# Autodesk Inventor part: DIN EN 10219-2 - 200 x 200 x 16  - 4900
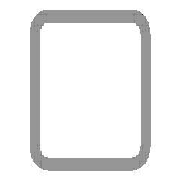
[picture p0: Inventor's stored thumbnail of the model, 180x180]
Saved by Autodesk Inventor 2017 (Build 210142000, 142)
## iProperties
IsCustomPart: 1
Created: 2017-11
Part Number: DIN EN 10219-2 - 200 x 200 x 16  - 4900
Material: Steel, Mild
Description: Cold formed welded structural hollow sections of non-alloy and fine grain structural steel
Document SubType Name: Modeling
Standard: DIN
Designer: iusti
Standard Revision: 2006-07
Standards Organization: DIN
Language: en-US
Size Designation: 200 x 200 x 16
Categories: <MemberInstance><Categories><Category DisplayName="Structural Shapes" InternalName="089c4875-fa83-4c05-b084-43b9cc11f5ed" Mnemonic="GRDR"><CategoryParameter Dis
Stock Number: 200 x 200 x 16
Density: 7.85 g/cm^3
Appearance: Semi-Polished
Mass: 410700 g
Surface Area: 65611.6 cm^2
Volume: 52318.5 cm^3
_CCFamilyMember: 103
_CCFamilyDisplayName: DIN EN 10219-2 (Square Hollow Section - Cold Formed) - Cold formed welded structural hollow sections of non-alloy and fine grain structural steel
_FrameMemberDoc: Frame Member File
_Version: 15.0.0
_GetPNFromCC: 1
G_L: 4900.000 mm
G_W: 200.000 mm
G_H: 200.000 mm
+07E149D3-E7B6-449F-B06C-092C84D7F120+CUTDETAIL1: Cut
Author: iusti
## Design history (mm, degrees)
node "Start plane"
node "End plane"
sketch "Sketch"
  geometry: L1 (-100, -52)-(-100, 52); L2 (-52, 100)-(52, 100); L3 (100, 52)-(100, -52); L4 (52, -100)-(-52, -100); L5 (-52, 84)-(52, 84); L6 (84, 52)-(84, -52); L7 (52, -84)-(-52, -84); L8 (-84, -52)-(-84, 52); L9 (0, 293.918)-(0, -293.918) reference; L10 (-293.918, 0)-(293.918, 0) reference; A1 r 48 centre (-52, -52) between (-100, -52) and (-52, -100); A2 r 48 centre (-52, 52) between (-52, 100) and (-100, 52); A3 r 48 centre (52, 52) between (100, 52) and (52, 100); A4 r 48 centre (52, -52) between (52, -100) and (100, -52); A5 r 32 centre (-52, 52) between (-52, 84) and (-84, 52); A6 r 32 centre (52, 52) between (84, 52) and (52, 84); A7 r 32 centre (52, -52) between (52, -84) and (84, -52); A8 r 32 centre (-52, -52) between (-84, -52) and (-52, -84)
  constraints: 16 end point, 16 point on circle, 8 centre point, 8 tangent, 4 parallel, 3 equal radius, 2 perpendicular, 7 other
  dimensions: "d7" = 48 radius of A1 (= G_IR); "d10" = 200 distance between parallel lines of L2 L4 (= G_H); "d11" = 200 distance between parallel lines of L1 L3 (= G_W); "d12" = 16 distance between parallel lines of L3 L6 (= G_T); "d15" = 100 distance between parallel lines of L2 L10 (= 0.5 x d10); "d16" = 100 distance between parallel lines of L9 L3 (= 0.5 x d11)
extrude "Body" new body sketch "Sketch" stored distance "d3" = 4900 (= G_L); taper "d4" = 0 deg
node "Driven Length"
  sketch "Sketch3"
    geometry: L1 (0, 0)-(10, 0) reference
    constraints: 2 end point, 1 horizontal
  workplane "Work Plane3"
  sketch "Sketch4"
    geometry: L1 (-2, 100)-(12, 100) reference; L2 (-2, 5000)-(12, 5000) reference
    dimensions: "d18" = 4900 distance between parallel lines of L1 L2 (derived)
workplane "Work Plane4"
split "Split1"
body "Solid1"
other parameters: "G_W" = 200 [user parameter; used in 1 equation term], "G_H" = 200 [user parameter; used in 1 equation term], "G_T" = 16 [user parameter; used in 1 equation term], "G_IR" = 48 [user parameter; used in 1 equation term], "G_L" = 4900 (= d18) [user parameter; used in 1 equation term], "G_OFFSET_END" = 0 [user parameter; used in 1 equation term], "d17" = 90 deg
